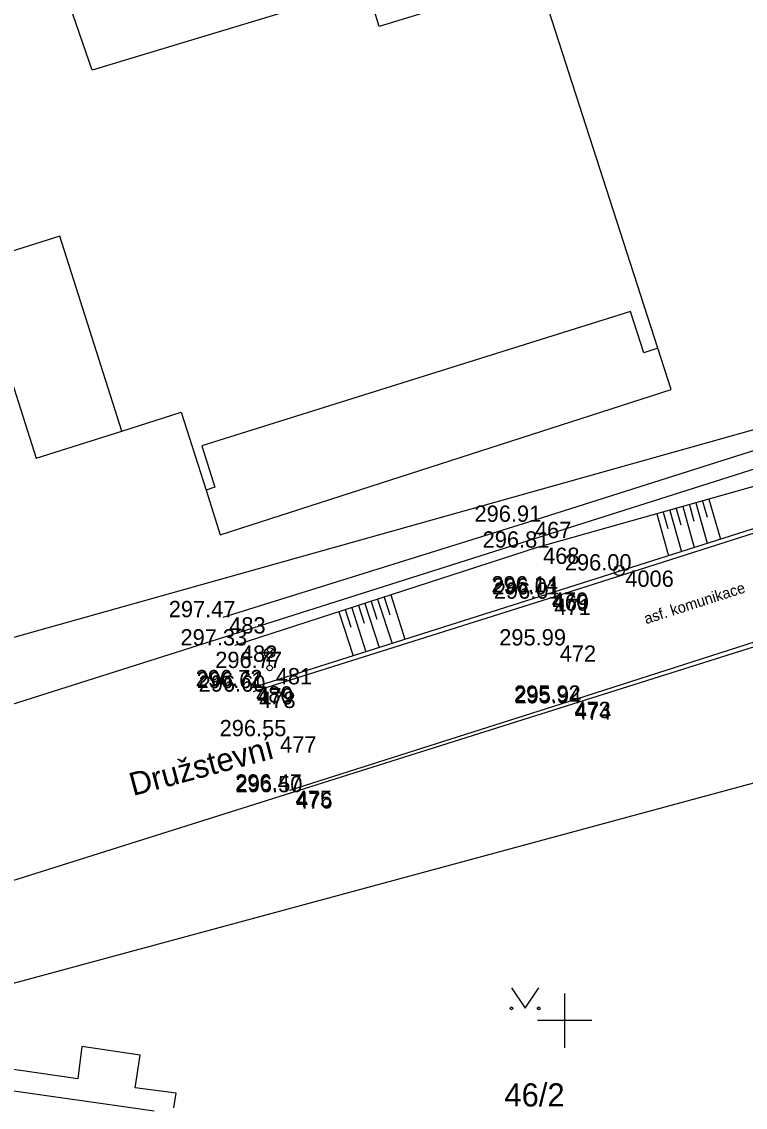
# Model space of a CAD drawing. Extents: x -599970 to -599524, y -1154772 to -1154457.
# Drawn here: x -599819.97 to -599793.37, y -1154703.19 to -1154663.25 of the extents above; entities that cross this region are included whole.
import ezdxf

# ---------------------------------------------------------------- set-up
doc = ezdxf.new("R2010")
doc.units = 0
for name, color, linetype in [('Z-ELEKTRICKE SKRINE LAMPY', 7, 'Continuous'), ('Z-KATASTRALNI MAPA', 7, 'Continuous'), ('Z-KRIZKY CTVERCOVE SITE', 7, 'Continuous'), ('Z-PEVNE BODY-CISLO', 7, 'Continuous'), ('Z-PEVNE BODY-VYSKA', 7, 'Continuous'), ('Z-PEVNE BODY-ZNACKA', 7, 'Continuous'), ('Z-PLOT DREVENY', 7, 'Continuous'), ('Z-PODROBNE BODY', 7, 'Continuous'), ('Z-PODROBNE BODY-CISLO', 7, 'Continuous'), ('Z-PODROBNE BODY-VYSKA', 7, 'Continuous'), ('Z-POPISY OBJEKTU A ZPEVNENYCH PLOCH', 7, 'Continuous'), ('Z-SRAFOVANI SVAHU', 7, 'Continuous'), ('Z-TERENNI HRANY PATY', 7, 'Continuous'), ('Z-ZPEVNENE PLOCHY', 7, 'Continuous')]:
    doc.layers.add(name, color=color, linetype=linetype)

msp = doc.modelspace()

# ---------------------------------------------------------------- linework, layer by layer
at = {"layer": 'Z-ELEKTRICKE SKRINE LAMPY'}
for p, q in [((-599810.982, -1154686.599), (-599810.718, -1154686.335)), ((-599810.714, -1154686.598), (-599810.978, -1154686.333)), ((-599810.85, -1154686.93), (-599810.85, -1154686.655))]:
    msp.add_line(p, q, dxfattribs=at)
for centre, radius in [((-599810.85, -1154686.468), 0.188), ((-599810.85, -1154687.03), 0.1)]:
    msp.add_circle(centre, radius, dxfattribs=at)
at = {"layer": 'Z-KATASTRALNI MAPA'}
for p, q in [((-599818.56, -1154671.14), (-599834.18, -1154676.08)), ((-599816.29, -1154678.31), (-599818.56, -1154671.14)), ((-599797.59, -1154673.91), (-599813.34, -1154678.85)), ((-599797.1, -1154675.43), (-599797.59, -1154673.91)), ((-599779.39, -1154675.37), (-599848.12, -1154697.2)), ((-599796.58, -1154675.26), (-599797.1, -1154675.43)), ((-599813.34, -1154678.85), (-599812.86, -1154680.37)), ((-599812.86, -1154680.37), (-599813.19, -1154680.48)), ((-599823.45, -1154699.48), (-599786.94, -1154689.6)), ((-599817.9, -1154702.14), (-599826.85, -1154700.87)), ((-599826.27, -1154701.73), (-599815.09, -1154703.32))]:
    msp.add_line(p, q, dxfattribs=at)
for points in [[(-599804.21, -1154662.63), (-599806.82, -1154663.42), (-599807.26, -1154661.96), (-599817.38, -1154665.03), (-599819.48, -1154658.91)], [(-599820.75, -1154675.17), (-599819.44, -1154679.31), (-599816.29, -1154678.31), (-599814.1, -1154677.62), (-599813.19, -1154680.48), (-599812.67, -1154682.13), (-599796.09, -1154676.78), (-599796.58, -1154675.26), (-599800.97, -1154661.65)], [(-599834.98, -1154699.48), (-599751.66, -1154673.18), (-599740.79, -1154669.9), (-599738.46, -1154669.48), (-599735.86, -1154669.61), (-599733.7, -1154670.53), (-599731.62, -1154671.85), (-599729.9, -1154673.34)], [(-599779.65, -1154674.5), (-599852.06, -1154694.84), (-599855.48, -1154695.93)], [(-599801.96, -1154698.799), (-599801.46, -1154699.55), (-599800.96, -1154698.799)], [(-599815.8, -1154702.47), (-599815.61, -1154701.27), (-599817.76, -1154700.96), (-599817.9, -1154702.14)], [(-599814.37, -1154703.21), (-599814.29, -1154702.67), (-599815.8, -1154702.47)]]:
    msp.add_lwpolyline(points, dxfattribs=at)
for centre in [(-599801.96, -1154699.55), (-599800.96, -1154699.55)]:
    msp.add_circle(centre, 0.05, dxfattribs=at)
at = {"layer": 'Z-KRIZKY CTVERCOVE SITE'}
for p, q in [((-599800, -1154701), (-599800, -1154699)), ((-599799, -1154700), (-599801, -1154700))]:
    msp.add_line(p, q, dxfattribs=at)
at = {"layer": 'Z-PEVNE BODY-ZNACKA'}
for radius in [0.188, 0.188, 0.00896, 0.00896]:
    msp.add_circle((-599798, -1154683.44), radius, dxfattribs=at)
at = {"layer": 'Z-PLOT DREVENY'}
msp.add_lwpolyline([(-599812.56, -1154685.16), (-599801.32, -1154681.65), (-599791.39, -1154678.5), (-599786.35, -1154676.9), (-599779.22, -1154674.68)], dxfattribs=at)
at = {"layer": 'Z-PODROBNE BODY'}
for p, q in [((-599801.32, -1154681.65), (-599801.32, -1154681.65)), ((-599801.02, -1154682.6), (-599801.02, -1154682.6)), ((-599800.7, -1154684.25), (-599800.7, -1154684.25)), ((-599800.67, -1154684.32), (-599800.67, -1154684.32)), ((-599800.61, -1154684.48), (-599800.61, -1154684.48)), ((-599812.56, -1154685.16), (-599812.56, -1154685.16)), ((-599812.13, -1154686.2), (-599812.13, -1154686.2)), ((-599800.41, -1154686.2), (-599800.41, -1154686.2)), ((-599810.85, -1154687.03), (-599810.85, -1154687.03)), ((-599811.57, -1154687.7), (-599811.57, -1154687.7)), ((-599811.53, -1154687.77), (-599811.53, -1154687.77)), ((-599811.46, -1154687.9), (-599811.46, -1154687.9)), ((-599799.87, -1154688.27), (-599799.87, -1154688.27)), ((-599799.85, -1154688.33), (-599799.85, -1154688.33)), ((-599810.69, -1154689.54), (-599810.69, -1154689.54)), ((-599810.12, -1154691.54), (-599810.12, -1154691.54)), ((-599810.1, -1154691.6), (-599810.1, -1154691.6))]:
    msp.add_line(p, q, dxfattribs=at)
at = {"layer": 'Z-SRAFOVANI SVAHU'}
for points in [[(-599795.66, -1154681.09), (-599795.24, -1154682.59)], [(-599795.42, -1154681.02), (-599795.25, -1154681.62)], [(-599795.18, -1154680.95), (-599794.76, -1154682.44)], [(-599794.94, -1154680.89), (-599794.77, -1154681.48)], [(-599794.7, -1154680.82), (-599794.28, -1154682.29)], [(-599796.62, -1154681.36), (-599796.19, -1154682.9)], [(-599796.38, -1154681.29), (-599796.21, -1154681.9)], [(-599796.14, -1154681.23), (-599795.71, -1154682.75)], [(-599795.9, -1154681.16), (-599795.73, -1154681.76)], [(-599806.4, -1154684.34), (-599805.88, -1154685.97)], [(-599807.59, -1154684.73), (-599807.38, -1154685.38)], [(-599807.35, -1154684.65), (-599806.83, -1154686.28)], [(-599807.12, -1154684.58), (-599806.91, -1154685.23)], [(-599806.88, -1154684.5), (-599806.35, -1154686.13)], [(-599806.64, -1154684.42), (-599806.43, -1154685.07)], [(-599808.31, -1154684.96), (-599807.78, -1154686.58)], [(-599808.07, -1154684.88), (-599807.86, -1154685.53)], [(-599807.83, -1154684.81), (-599807.31, -1154686.43)]]:
    msp.add_lwpolyline(points, dxfattribs=at)
at = {"layer": 'Z-TERENNI HRANY PATY'}
msp.add_lwpolyline([(-599778.47, -1154675.47), (-599786.05, -1154677.74), (-599791.05, -1154679.79), (-599801.02, -1154682.6), (-599812.13, -1154686.2)], dxfattribs=at)
at = {"layer": 'Z-ZPEVNENE PLOCHY'}
for points in [[(-599772.85, -1154675.54), (-599776.28, -1154676.63), (-599778.05, -1154677.18), (-599785.5, -1154679.52), (-599790.53, -1154681.1), (-599800.67, -1154684.32), (-599811.53, -1154687.77)], [(-599772.99, -1154675.74), (-599776.22, -1154676.81), (-599777.99, -1154677.34), (-599785.42, -1154679.68), (-599790.47, -1154681.24), (-599800.61, -1154684.48), (-599811.46, -1154687.9)], [(-599771.9, -1154679.45), (-599776.08, -1154680.75), (-599782.88, -1154682.88), (-599783.87, -1154683.12), (-599785.23, -1154683.58), (-599786.18, -1154683.89), (-599788.07, -1154684.53), (-599789.03, -1154684.79), (-599799.87, -1154688.27), (-599810.12, -1154691.54)]]:
    msp.add_lwpolyline(points, dxfattribs=at)

# ---------------------------------------------------------------- texts
at = {"layer": 'Z-KATASTRALNI MAPA'}
msp.add_text('Družstevní', height=0.85, rotation=15, dxfattribs=at).set_placement((-599815.874, -1154691.743))
msp.add_text('46/2', height=0.85, dxfattribs=at).set_placement((-599802.219, -1154703.16))
at = {"layer": 'Z-PEVNE BODY-CISLO'}
msp.add_text(' 4006', height=0.6, dxfattribs=at).set_placement((-599798, -1154684.04))
at = {"layer": 'Z-PEVNE BODY-VYSKA'}
msp.add_text('296.00 ', height=0.6, dxfattribs=at).set_placement((-599800, -1154683.44))
at = {"layer": 'Z-PODROBNE BODY-CISLO'}
for s, p in [(' 467', (-599801.32, -1154682.25)), (' 468', (-599801.02, -1154683.2)), (' 470', (-599800.7, -1154684.85)), (' 469', (-599800.67, -1154684.92)), (' 471', (-599800.61, -1154685.08)), (' 483', (-599812.56, -1154685.76)), (' 482', (-599812.13, -1154686.8)), (' 472', (-599800.41, -1154686.8)), (' 481', (-599810.85, -1154687.63)), (' 480', (-599811.57, -1154688.3)), (' 479', (-599811.53, -1154688.37)), (' 478', (-599811.46, -1154688.5)), (' 473', (-599799.87, -1154688.87)), (' 474', (-599799.85, -1154688.93)), (' 477', (-599810.69, -1154690.14)), (' 475', (-599810.12, -1154692.14)), (' 476', (-599810.1, -1154692.2))]:
    msp.add_text(s, height=0.6, dxfattribs=at).set_placement(p)
at = {"layer": 'Z-PODROBNE BODY-VYSKA'}
for s, p in [('296.91 ', (-599803.32, -1154681.65)), ('296.81 ', (-599803.02, -1154682.6)), ('296.14 ', (-599802.7, -1154684.25)), ('296.01 ', (-599802.67, -1154684.32)), ('296.01 ', (-599802.61, -1154684.48)), ('297.47 ', (-599814.56, -1154685.16)), ('297.33 ', (-599814.13, -1154686.2)), ('295.99 ', (-599802.41, -1154686.2)), ('296.77 ', (-599812.85, -1154687.03)), ('296.72 ', (-599813.57, -1154687.7)), ('296.61 ', (-599813.53, -1154687.77)), ('296.60 ', (-599813.46, -1154687.9)), ('295.92 ', (-599801.87, -1154688.27)), ('295.94 ', (-599801.85, -1154688.33)), ('296.55 ', (-599812.69, -1154689.54)), ('296.47 ', (-599812.12, -1154691.54)), ('296.50 ', (-599812.1, -1154691.6))]:
    msp.add_text(s, height=0.6, dxfattribs=at).set_placement(p)
at = {"layer": 'Z-POPISY OBJEKTU A ZPEVNENYCH PLOCH'}
msp.add_text('asf. komunikace', height=0.4, rotation=17.7984, dxfattribs=at).set_placement((-599797.01, -1154685.42))

doc.saveas('drawing.dxf')
